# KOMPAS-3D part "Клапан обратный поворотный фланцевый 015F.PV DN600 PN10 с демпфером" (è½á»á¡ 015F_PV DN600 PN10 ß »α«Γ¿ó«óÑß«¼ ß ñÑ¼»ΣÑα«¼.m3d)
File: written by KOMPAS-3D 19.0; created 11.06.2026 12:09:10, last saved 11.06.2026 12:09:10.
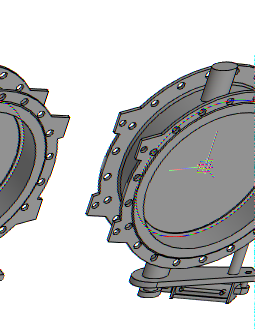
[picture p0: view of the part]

Document properties: Автор: Энергия; Полное имя файла: Z:\3.Личные\kachalov\001_3d для проектировщиков\5.5 Тип 015F.PV Клапан обратный поворотный с двумя эксцентриками\_stp_Клапан 015F.PV DN300-DN1200 с противовесом с демпфером\Клапан 015F_PV DN600 PN10 с противовесом с демпфером.m3d

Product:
- Part/product: Клапан обратный поворотный фланцевый 015F.PV DN600 PN10 с демпфером

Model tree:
1. Операция без истории:1
2. Сплайн:1
     Координата Y = 30; Координата Z = 300; Вес = 1; Координата X = 600; Координата Y = 108.991; Координата Z = 300; Вес = 0.333333; Координата X = 600; Координата Y = 108.991; Координата Z = -300; Вес = 0.333333; Координата Y = 30; Координата Z = -300; Вес = 1; Координата X = -600; Координата Y = -48.9915; Координата Z = -300; Вес = 0.333333; Координата X = -600; Координата Y = -48.9915; Координата Z = 300; Вес = 0.333333; Порядок = 4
